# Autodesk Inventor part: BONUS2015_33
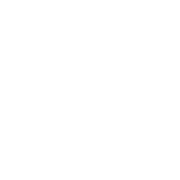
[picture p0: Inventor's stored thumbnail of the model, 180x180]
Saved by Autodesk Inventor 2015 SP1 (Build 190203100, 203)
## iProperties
Created: 2015-05
Part Number: BONUS2015_33
Material: Generisch
Document SubType Name: Modeling
Density: 1 g/cm^3
Appearance: Vorgabe
xx: 33
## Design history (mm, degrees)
